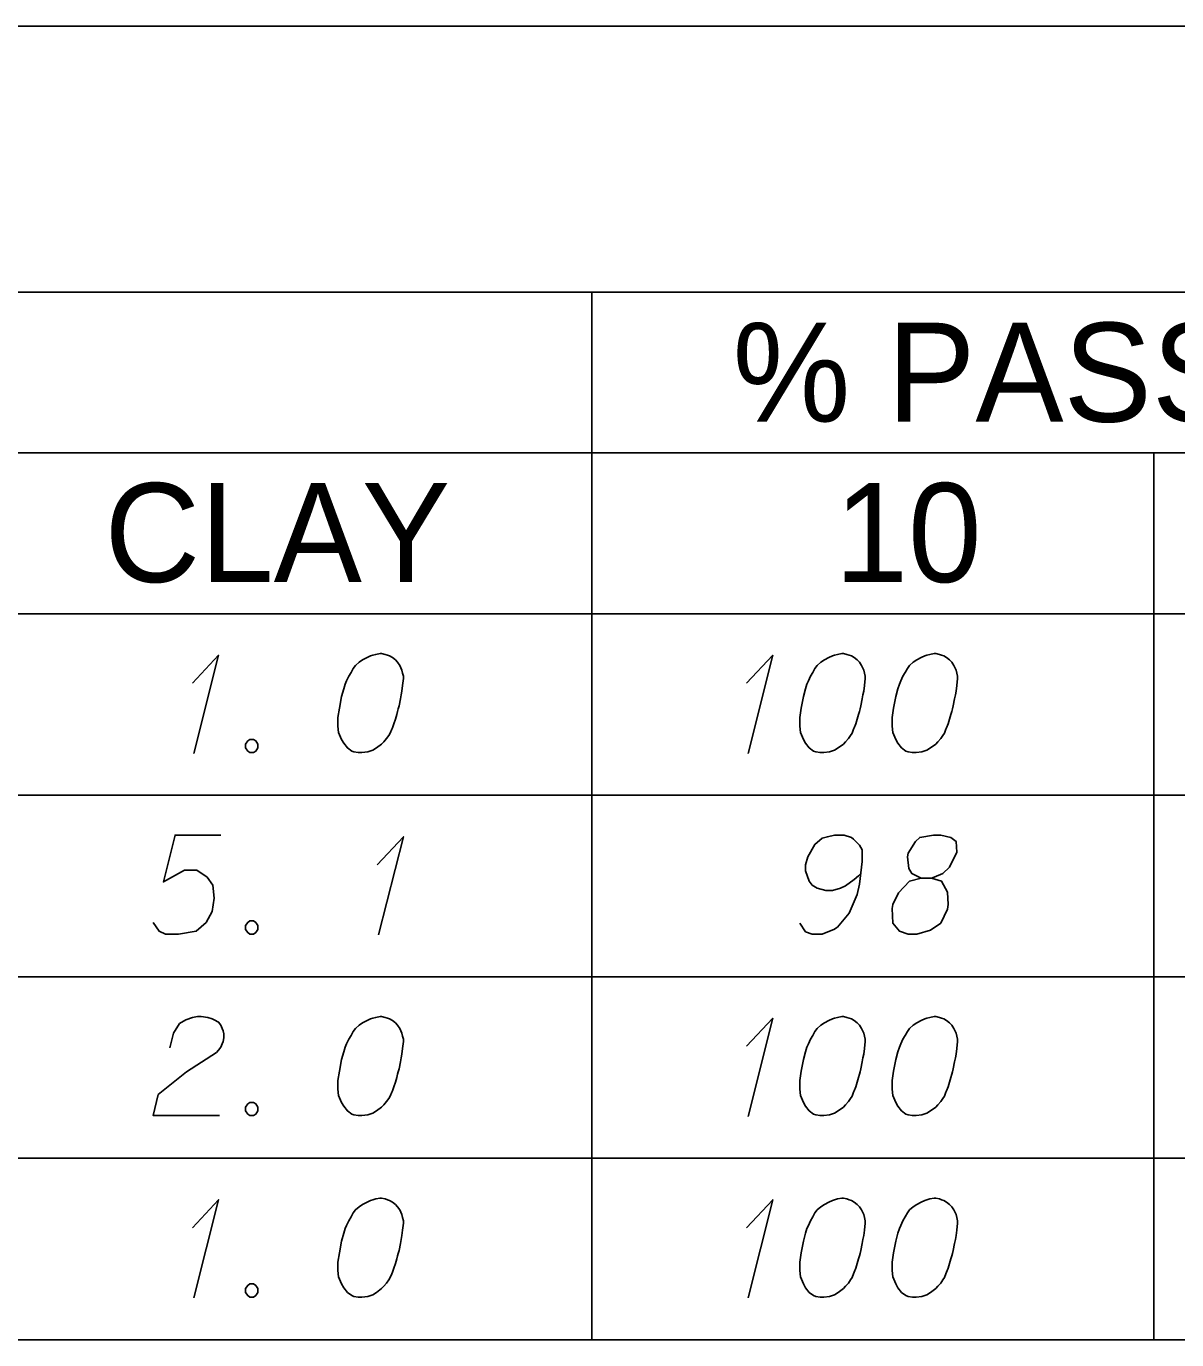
# Model space of a CAD drawing. Extents: x 2074207 to 2076812, y 516372 to 523312.
# Drawn here: x 2076622.7 to 2076678.5, y 516601.5 to 516665.2 of the extents above; entities that cross this region are included whole.
import ezdxf

# ---------------------------------------------------------------- set-up
doc = ezdxf.new("R2010")
doc.units = 0
for name, color, linetype in [('Prop DirtTable_ Soil Test Results - Outline (Major)', 7, 'Continuous'), ('Prop DirtTable_ Soil Test Results - Outline (Minor)', 7, 'Continuous'), ('Prop DirtTable_ Soil Test Results - Tx (Header - Small)', 7, 'Continuous'), ('Prop DirtTable_ Soil Test Results - Tx (Sample Data)', 7, 'Continuous')]:
    doc.layers.add(name, color=color, linetype=linetype)

msp = doc.modelspace()

# ---------------------------------------------------------------- linework, layer by layer
at = {"layer": 'Prop DirtTable_ Soil Test Results - Outline (Major)'}
for p, q in [((2076260.609, 516665.206), (2076811.903, 516665.206)), ((2076260.609, 516636.721), (2076811.903, 516636.721)), ((2076260.609, 516636.721), (2076811.903, 516636.721)), ((2076260.609, 516601.521), (2076811.903, 516601.521))]:
    msp.add_line(p, q, dxfattribs=at)
at = {"layer": 'Prop DirtTable_ Soil Test Results - Outline (Minor)'}
for p, q in [((2076260.609, 516652.321), (2076811.903, 516652.321)), ((2076650.154, 516652.321), (2076650.154, 516627.921)), ((2076526.074, 516644.521), (2076731.93, 516644.521)), ((2076677.413, 516644.521), (2076677.413, 516627.921)), ((2076260.609, 516627.921), (2076811.903, 516627.921)), ((2076260.609, 516627.921), (2076811.903, 516627.921)), ((2076650.154, 516627.921), (2076650.154, 516619.121)), ((2076677.413, 516627.921), (2076677.413, 516619.121)), ((2076260.609, 516619.121), (2076811.903, 516619.121)), ((2076260.609, 516619.121), (2076811.903, 516619.121)), ((2076650.154, 516619.121), (2076650.154, 516610.321)), ((2076677.413, 516619.121), (2076677.413, 516610.321)), ((2076260.609, 516610.321), (2076811.903, 516610.321)), ((2076260.609, 516610.321), (2076811.903, 516610.321)), ((2076650.154, 516610.321), (2076650.154, 516601.521)), ((2076677.413, 516610.321), (2076677.413, 516601.521)), ((2076260.609, 516601.521), (2076811.903, 516601.521))]:
    msp.add_line(p, q, dxfattribs=at)
at = {"layer": 'Prop DirtTable_ Soil Test Results - Tx (Sample Data)'}
for points in [[(2076630.78, 516633.35), (2076632.05, 516634.711), (2076630.851, 516629.948)], [(2076639.952, 516634.786), (2076639.882, 516634.786), (2076639.67, 516634.748), (2076639.529, 516634.711), (2076639.423, 516634.673), (2076639.247, 516634.597), (2076639.035, 516634.484), (2076638.859, 516634.37), (2076638.682, 516634.219), (2076638.576, 516634.068), (2076638.471, 516633.879), (2076638.365, 516633.69), (2076638.259, 516633.463), (2076638.188, 516633.312), (2076638.118, 516633.085), (2076638.012, 516632.707), (2076637.906, 516632.141), (2076637.836, 516631.687), (2076637.836, 516631.271), (2076637.871, 516630.969), (2076638.012, 516630.629), (2076638.118, 516630.44), (2076638.294, 516630.213), (2076638.506, 516630.062), (2076638.612, 516630.024), (2076638.823, 516629.986), (2076639, 516629.986), (2076639.282, 516630.024), (2076639.529, 516630.1), (2076639.705, 516630.213), (2076639.952, 516630.402), (2076640.058, 516630.515), (2076640.199, 516630.666), (2076640.305, 516630.818), (2076640.375, 516630.931), (2076640.446, 516631.12), (2076640.481, 516631.196), (2076640.552, 516631.385), (2076640.622, 516631.611), (2076640.693, 516631.838), (2076640.728, 516631.989), (2076640.763, 516632.103), (2076640.799, 516632.254), (2076640.869, 516632.594), (2076640.905, 516632.783), (2076640.94, 516632.972), (2076640.975, 516633.237), (2076641.01, 516633.577), (2076641.01, 516633.69), (2076640.975, 516633.841), (2076640.94, 516633.992), (2076640.834, 516634.219), (2076640.728, 516634.37), (2076640.622, 516634.484), (2076640.481, 516634.597), (2076640.34, 516634.673), (2076640.234, 516634.711), (2076640.129, 516634.748), (2076639.952, 516634.786)], [(2076657.66, 516633.35), (2076658.93, 516634.711), (2076657.731, 516629.948)], [(2076662.352, 516634.786), (2076662.282, 516634.786), (2076662.07, 516634.748), (2076661.929, 516634.711), (2076661.823, 516634.673), (2076661.647, 516634.597), (2076661.435, 516634.484), (2076661.259, 516634.37), (2076661.082, 516634.219), (2076660.976, 516634.068), (2076660.871, 516633.879), (2076660.765, 516633.69), (2076660.659, 516633.463), (2076660.588, 516633.312), (2076660.518, 516633.085), (2076660.412, 516632.707), (2076660.306, 516632.141), (2076660.236, 516631.687), (2076660.236, 516631.271), (2076660.271, 516630.969), (2076660.412, 516630.629), (2076660.518, 516630.44), (2076660.694, 516630.213), (2076660.906, 516630.062), (2076661.012, 516630.024), (2076661.223, 516629.986), (2076661.4, 516629.986), (2076661.682, 516630.024), (2076661.929, 516630.1), (2076662.105, 516630.213), (2076662.352, 516630.402), (2076662.458, 516630.515), (2076662.599, 516630.666), (2076662.705, 516630.818), (2076662.775, 516630.931), (2076662.846, 516631.12), (2076662.881, 516631.196), (2076662.952, 516631.385), (2076663.022, 516631.611), (2076663.093, 516631.838), (2076663.128, 516631.989), (2076663.163, 516632.103), (2076663.199, 516632.254), (2076663.269, 516632.594), (2076663.305, 516632.783), (2076663.34, 516632.972), (2076663.375, 516633.237), (2076663.41, 516633.577), (2076663.41, 516633.69), (2076663.375, 516633.841), (2076663.34, 516633.992), (2076663.234, 516634.219), (2076663.128, 516634.37), (2076663.022, 516634.484), (2076662.881, 516634.597), (2076662.74, 516634.673), (2076662.634, 516634.711), (2076662.529, 516634.748), (2076662.352, 516634.786)], [(2076666.832, 516634.786), (2076666.762, 516634.786), (2076666.55, 516634.748), (2076666.409, 516634.711), (2076666.303, 516634.673), (2076666.127, 516634.597), (2076665.915, 516634.484), (2076665.739, 516634.37), (2076665.562, 516634.219), (2076665.456, 516634.068), (2076665.351, 516633.879), (2076665.245, 516633.69), (2076665.139, 516633.463), (2076665.068, 516633.312), (2076664.998, 516633.085), (2076664.892, 516632.707), (2076664.786, 516632.141), (2076664.716, 516631.687), (2076664.716, 516631.271), (2076664.751, 516630.969), (2076664.892, 516630.629), (2076664.998, 516630.44), (2076665.174, 516630.213), (2076665.386, 516630.062), (2076665.492, 516630.024), (2076665.703, 516629.986), (2076665.88, 516629.986), (2076666.162, 516630.024), (2076666.409, 516630.1), (2076666.585, 516630.213), (2076666.832, 516630.402), (2076666.938, 516630.515), (2076667.079, 516630.666), (2076667.185, 516630.818), (2076667.255, 516630.931), (2076667.326, 516631.12), (2076667.361, 516631.196), (2076667.432, 516631.385), (2076667.502, 516631.611), (2076667.573, 516631.838), (2076667.608, 516631.989), (2076667.643, 516632.103), (2076667.679, 516632.254), (2076667.749, 516632.594), (2076667.785, 516632.783), (2076667.82, 516632.972), (2076667.855, 516633.237), (2076667.89, 516633.577), (2076667.89, 516633.69), (2076667.855, 516633.841), (2076667.82, 516633.992), (2076667.714, 516634.219), (2076667.608, 516634.37), (2076667.502, 516634.484), (2076667.361, 516634.597), (2076667.22, 516634.673), (2076667.114, 516634.711), (2076667.009, 516634.748), (2076666.832, 516634.786)], [(2076633.567, 516630.629), (2076633.744, 516630.629), (2076633.849, 516630.553), (2076633.955, 516630.402), (2076633.955, 516630.213), (2076633.849, 516630.062), (2076633.744, 516629.986), (2076633.567, 516629.986), (2076633.461, 516630.062), (2076633.356, 516630.213), (2076633.356, 516630.402), (2076633.461, 516630.553), (2076633.567, 516630.629)], [(2076632.156, 516625.986), (2076629.934, 516625.986), (2076629.369, 516623.718), (2076630.392, 516624.285), (2076630.992, 516624.285), (2076631.486, 516623.945), (2076631.768, 516623.567), (2076631.839, 516622.925), (2076631.733, 516622.282), (2076631.451, 516621.753), (2076630.957, 516621.337), (2076630.11, 516621.186), (2076629.475, 516621.186), (2076629.158, 516621.337), (2076628.876, 516621.753)], [(2076639.74, 516624.55), (2076641.01, 516625.911), (2076639.811, 516621.148)], [(2076660.236, 516621.715), (2076660.518, 516621.3), (2076660.835, 516621.186), (2076661.329, 516621.186), (2076661.682, 516621.337), (2076661.894, 516621.413), (2076662.07, 516621.526), (2076662.634, 516622.207), (2076663.022, 516623.114), (2076663.128, 516623.605), (2076663.269, 516624.701), (2076663.269, 516625.268), (2076663.128, 516625.495), (2076662.846, 516625.797), (2076662.74, 516625.873), (2076662.387, 516625.986), (2076661.929, 516625.986), (2076661.576, 516625.911), (2076661.329, 516625.835), (2076660.976, 516625.533), (2076660.624, 516624.928), (2076660.518, 516624.55), (2076660.518, 516624.248), (2076660.694, 516623.756), (2076660.835, 516623.567), (2076661.082, 516623.416), (2076661.506, 516623.303), (2076661.823, 516623.303), (2076662.211, 516623.416), (2076662.458, 516623.529), (2076662.881, 516623.832), (2076663.093, 516624.021), (2076663.199, 516624.134)], [(2076666.127, 516623.907), (2076666.62, 516623.907), (2076666.762, 516623.945), (2076667.185, 516624.134), (2076667.502, 516624.437), (2076667.855, 516625.155), (2076667.82, 516625.684), (2076667.573, 516625.873), (2076667.079, 516625.986), (2076666.726, 516625.986), (2076666.056, 516625.873), (2076665.844, 516625.684), (2076665.492, 516625.117), (2076665.456, 516624.928), (2076665.527, 516624.361), (2076665.668, 516624.134), (2076666.127, 516623.907), (2076665.562, 516623.756), (2076665.033, 516623.189), (2076664.751, 516622.622), (2076664.716, 516622.433), (2076664.751, 516621.715), (2076665.068, 516621.337), (2076665.492, 516621.186), (2076665.915, 516621.186), (2076666.585, 516621.375), (2076667.079, 516621.715), (2076667.397, 516622.396), (2076667.432, 516622.622), (2076667.397, 516623.227), (2076667.114, 516623.756), (2076666.62, 516623.907)], [(2076633.567, 516621.829), (2076633.744, 516621.829), (2076633.849, 516621.753), (2076633.955, 516621.602), (2076633.955, 516621.413), (2076633.849, 516621.262), (2076633.744, 516621.186), (2076633.567, 516621.186), (2076633.461, 516621.262), (2076633.356, 516621.413), (2076633.356, 516621.602), (2076633.461, 516621.753), (2076633.567, 516621.829)], [(2076629.687, 516615.674), (2076629.863, 516616.392), (2076630.146, 516616.846), (2076630.463, 516617.035), (2076630.78, 516617.148), (2076631.027, 516617.186), (2076631.204, 516617.186), (2076631.521, 516617.148), (2076631.733, 516617.073), (2076631.839, 516617.035), (2076632.05, 516616.922), (2076632.156, 516616.77), (2076632.227, 516616.619), (2076632.262, 516616.506), (2076632.297, 516616.355), (2076632.297, 516616.166), (2076632.262, 516615.977), (2076632.227, 516615.863), (2076632.156, 516615.712), (2076632.05, 516615.561), (2076631.945, 516615.448), (2076630.498, 516614.503), (2076629.123, 516613.407), (2076628.876, 516612.386), (2076632.086, 516612.386)], [(2076639.952, 516617.186), (2076639.882, 516617.186), (2076639.67, 516617.148), (2076639.529, 516617.111), (2076639.423, 516617.073), (2076639.247, 516616.997), (2076639.035, 516616.884), (2076638.859, 516616.77), (2076638.682, 516616.619), (2076638.576, 516616.468), (2076638.471, 516616.279), (2076638.365, 516616.09), (2076638.259, 516615.863), (2076638.188, 516615.712), (2076638.118, 516615.485), (2076638.012, 516615.107), (2076637.906, 516614.541), (2076637.836, 516614.087), (2076637.836, 516613.671), (2076637.871, 516613.369), (2076638.012, 516613.029), (2076638.118, 516612.84), (2076638.294, 516612.613), (2076638.506, 516612.462), (2076638.612, 516612.424), (2076638.823, 516612.386), (2076639, 516612.386), (2076639.282, 516612.424), (2076639.529, 516612.5), (2076639.705, 516612.613), (2076639.952, 516612.802), (2076640.058, 516612.915), (2076640.199, 516613.066), (2076640.305, 516613.218), (2076640.375, 516613.331), (2076640.446, 516613.52), (2076640.481, 516613.596), (2076640.552, 516613.785), (2076640.622, 516614.011), (2076640.693, 516614.238), (2076640.728, 516614.389), (2076640.763, 516614.503), (2076640.799, 516614.654), (2076640.869, 516614.994), (2076640.905, 516615.183), (2076640.94, 516615.372), (2076640.975, 516615.637), (2076641.01, 516615.977), (2076641.01, 516616.09), (2076640.975, 516616.241), (2076640.94, 516616.392), (2076640.834, 516616.619), (2076640.728, 516616.77), (2076640.622, 516616.884), (2076640.481, 516616.997), (2076640.34, 516617.073), (2076640.234, 516617.111), (2076640.129, 516617.148), (2076639.952, 516617.186)], [(2076657.66, 516615.75), (2076658.93, 516617.111), (2076657.731, 516612.348)], [(2076662.352, 516617.186), (2076662.282, 516617.186), (2076662.07, 516617.148), (2076661.929, 516617.111), (2076661.823, 516617.073), (2076661.647, 516616.997), (2076661.435, 516616.884), (2076661.259, 516616.77), (2076661.082, 516616.619), (2076660.976, 516616.468), (2076660.871, 516616.279), (2076660.765, 516616.09), (2076660.659, 516615.863), (2076660.588, 516615.712), (2076660.518, 516615.485), (2076660.412, 516615.107), (2076660.306, 516614.541), (2076660.236, 516614.087), (2076660.236, 516613.671), (2076660.271, 516613.369), (2076660.412, 516613.029), (2076660.518, 516612.84), (2076660.694, 516612.613), (2076660.906, 516612.462), (2076661.012, 516612.424), (2076661.223, 516612.386), (2076661.4, 516612.386), (2076661.682, 516612.424), (2076661.929, 516612.5), (2076662.105, 516612.613), (2076662.352, 516612.802), (2076662.458, 516612.915), (2076662.599, 516613.066), (2076662.705, 516613.218), (2076662.775, 516613.331), (2076662.846, 516613.52), (2076662.881, 516613.596), (2076662.952, 516613.785), (2076663.022, 516614.011), (2076663.093, 516614.238), (2076663.128, 516614.389), (2076663.163, 516614.503), (2076663.199, 516614.654), (2076663.269, 516614.994), (2076663.305, 516615.183), (2076663.34, 516615.372), (2076663.375, 516615.637), (2076663.41, 516615.977), (2076663.41, 516616.09), (2076663.375, 516616.241), (2076663.34, 516616.392), (2076663.234, 516616.619), (2076663.128, 516616.77), (2076663.022, 516616.884), (2076662.881, 516616.997), (2076662.74, 516617.073), (2076662.634, 516617.111), (2076662.529, 516617.148), (2076662.352, 516617.186)], [(2076666.832, 516617.186), (2076666.762, 516617.186), (2076666.55, 516617.148), (2076666.409, 516617.111), (2076666.303, 516617.073), (2076666.127, 516616.997), (2076665.915, 516616.884), (2076665.739, 516616.77), (2076665.562, 516616.619), (2076665.456, 516616.468), (2076665.351, 516616.279), (2076665.245, 516616.09), (2076665.139, 516615.863), (2076665.068, 516615.712), (2076664.998, 516615.485), (2076664.892, 516615.107), (2076664.786, 516614.541), (2076664.716, 516614.087), (2076664.716, 516613.671), (2076664.751, 516613.369), (2076664.892, 516613.029), (2076664.998, 516612.84), (2076665.174, 516612.613), (2076665.386, 516612.462), (2076665.492, 516612.424), (2076665.703, 516612.386), (2076665.88, 516612.386), (2076666.162, 516612.424), (2076666.409, 516612.5), (2076666.585, 516612.613), (2076666.832, 516612.802), (2076666.938, 516612.915), (2076667.079, 516613.066), (2076667.185, 516613.218), (2076667.255, 516613.331), (2076667.326, 516613.52), (2076667.361, 516613.596), (2076667.432, 516613.785), (2076667.502, 516614.011), (2076667.573, 516614.238), (2076667.608, 516614.389), (2076667.643, 516614.503), (2076667.679, 516614.654), (2076667.749, 516614.994), (2076667.785, 516615.183), (2076667.82, 516615.372), (2076667.855, 516615.637), (2076667.89, 516615.977), (2076667.89, 516616.09), (2076667.855, 516616.241), (2076667.82, 516616.392), (2076667.714, 516616.619), (2076667.608, 516616.77), (2076667.502, 516616.884), (2076667.361, 516616.997), (2076667.22, 516617.073), (2076667.114, 516617.111), (2076667.009, 516617.148), (2076666.832, 516617.186)], [(2076633.567, 516613.029), (2076633.744, 516613.029), (2076633.849, 516612.953), (2076633.955, 516612.802), (2076633.955, 516612.613), (2076633.849, 516612.462), (2076633.744, 516612.386), (2076633.567, 516612.386), (2076633.461, 516612.462), (2076633.356, 516612.613), (2076633.356, 516612.802), (2076633.461, 516612.953), (2076633.567, 516613.029)], [(2076639.952, 516608.386), (2076639.882, 516608.386), (2076639.67, 516608.348), (2076639.529, 516608.311), (2076639.423, 516608.273), (2076639.247, 516608.197), (2076639.035, 516608.084), (2076638.859, 516607.97), (2076638.682, 516607.819), (2076638.576, 516607.668), (2076638.471, 516607.479), (2076638.365, 516607.29), (2076638.259, 516607.063), (2076638.188, 516606.912), (2076638.118, 516606.685), (2076638.012, 516606.307), (2076637.906, 516605.741), (2076637.836, 516605.287), (2076637.836, 516604.871), (2076637.871, 516604.569), (2076638.012, 516604.229), (2076638.118, 516604.04), (2076638.294, 516603.813), (2076638.506, 516603.662), (2076638.612, 516603.624), (2076638.823, 516603.586), (2076639, 516603.586), (2076639.282, 516603.624), (2076639.529, 516603.7), (2076639.705, 516603.813), (2076639.952, 516604.002), (2076640.058, 516604.115), (2076640.199, 516604.266), (2076640.305, 516604.418), (2076640.375, 516604.531), (2076640.446, 516604.72), (2076640.481, 516604.796), (2076640.552, 516604.985), (2076640.622, 516605.211), (2076640.693, 516605.438), (2076640.728, 516605.589), (2076640.763, 516605.703), (2076640.799, 516605.854), (2076640.869, 516606.194), (2076640.905, 516606.383), (2076640.94, 516606.572), (2076640.975, 516606.837), (2076641.01, 516607.177), (2076641.01, 516607.29), (2076640.975, 516607.441), (2076640.94, 516607.592), (2076640.834, 516607.819), (2076640.728, 516607.97), (2076640.622, 516608.084), (2076640.481, 516608.197), (2076640.34, 516608.273), (2076640.234, 516608.311), (2076640.129, 516608.348), (2076639.952, 516608.386)], [(2076662.352, 516608.386), (2076662.282, 516608.386), (2076662.07, 516608.348), (2076661.929, 516608.311), (2076661.823, 516608.273), (2076661.647, 516608.197), (2076661.435, 516608.084), (2076661.259, 516607.97), (2076661.082, 516607.819), (2076660.976, 516607.668), (2076660.871, 516607.479), (2076660.765, 516607.29), (2076660.659, 516607.063), (2076660.588, 516606.912), (2076660.518, 516606.685), (2076660.412, 516606.307), (2076660.306, 516605.741), (2076660.236, 516605.287), (2076660.236, 516604.871), (2076660.271, 516604.569), (2076660.412, 516604.229), (2076660.518, 516604.04), (2076660.694, 516603.813), (2076660.906, 516603.662), (2076661.012, 516603.624), (2076661.223, 516603.586), (2076661.4, 516603.586), (2076661.682, 516603.624), (2076661.929, 516603.7), (2076662.105, 516603.813), (2076662.352, 516604.002), (2076662.458, 516604.115), (2076662.599, 516604.266), (2076662.705, 516604.418), (2076662.775, 516604.531), (2076662.846, 516604.72), (2076662.881, 516604.796), (2076662.952, 516604.985), (2076663.022, 516605.211), (2076663.093, 516605.438), (2076663.128, 516605.589), (2076663.163, 516605.703), (2076663.199, 516605.854), (2076663.269, 516606.194), (2076663.305, 516606.383), (2076663.34, 516606.572), (2076663.375, 516606.837), (2076663.41, 516607.177), (2076663.41, 516607.29), (2076663.375, 516607.441), (2076663.34, 516607.592), (2076663.234, 516607.819), (2076663.128, 516607.97), (2076663.022, 516608.084), (2076662.881, 516608.197), (2076662.74, 516608.273), (2076662.634, 516608.311), (2076662.529, 516608.348), (2076662.352, 516608.386)], [(2076666.832, 516608.386), (2076666.762, 516608.386), (2076666.55, 516608.348), (2076666.409, 516608.311), (2076666.303, 516608.273), (2076666.127, 516608.197), (2076665.915, 516608.084), (2076665.739, 516607.97), (2076665.562, 516607.819), (2076665.456, 516607.668), (2076665.351, 516607.479), (2076665.245, 516607.29), (2076665.139, 516607.063), (2076665.068, 516606.912), (2076664.998, 516606.685), (2076664.892, 516606.307), (2076664.786, 516605.741), (2076664.716, 516605.287), (2076664.716, 516604.871), (2076664.751, 516604.569), (2076664.892, 516604.229), (2076664.998, 516604.04), (2076665.174, 516603.813), (2076665.386, 516603.662), (2076665.492, 516603.624), (2076665.703, 516603.586), (2076665.88, 516603.586), (2076666.162, 516603.624), (2076666.409, 516603.7), (2076666.585, 516603.813), (2076666.832, 516604.002), (2076666.938, 516604.115), (2076667.079, 516604.266), (2076667.185, 516604.418), (2076667.255, 516604.531), (2076667.326, 516604.72), (2076667.361, 516604.796), (2076667.432, 516604.985), (2076667.502, 516605.211), (2076667.573, 516605.438), (2076667.608, 516605.589), (2076667.643, 516605.703), (2076667.679, 516605.854), (2076667.749, 516606.194), (2076667.785, 516606.383), (2076667.82, 516606.572), (2076667.855, 516606.837), (2076667.89, 516607.177), (2076667.89, 516607.29), (2076667.855, 516607.441), (2076667.82, 516607.592), (2076667.714, 516607.819), (2076667.608, 516607.97), (2076667.502, 516608.084), (2076667.361, 516608.197), (2076667.22, 516608.273), (2076667.114, 516608.311), (2076667.009, 516608.348), (2076666.832, 516608.386)], [(2076630.78, 516606.95), (2076632.05, 516608.311), (2076630.851, 516603.548)], [(2076657.66, 516606.95), (2076658.93, 516608.311), (2076657.731, 516603.548)], [(2076633.567, 516604.229), (2076633.744, 516604.229), (2076633.849, 516604.153), (2076633.955, 516604.002), (2076633.955, 516603.813), (2076633.849, 516603.662), (2076633.744, 516603.586), (2076633.567, 516603.586), (2076633.461, 516603.662), (2076633.356, 516603.813), (2076633.356, 516604.002), (2076633.461, 516604.153), (2076633.567, 516604.229)]]:
    msp.add_lwpolyline(points, dxfattribs=at)

# ---------------------------------------------------------------- texts
at = {"layer": 'Prop DirtTable_ Soil Test Results - Tx (Header - Small)'}
for s, height, p in [('% PASSING (SIEVES)', 4.79998, (2076656.984, 516646.031)), ('CLAY', 4.8, (2076626.513, 516638.256)), ('10', 4.8, (2076661.92, 516638.256))]:
    msp.add_text(s, height=height, dxfattribs=at).set_placement(p)

doc.saveas('drawing.dxf')
